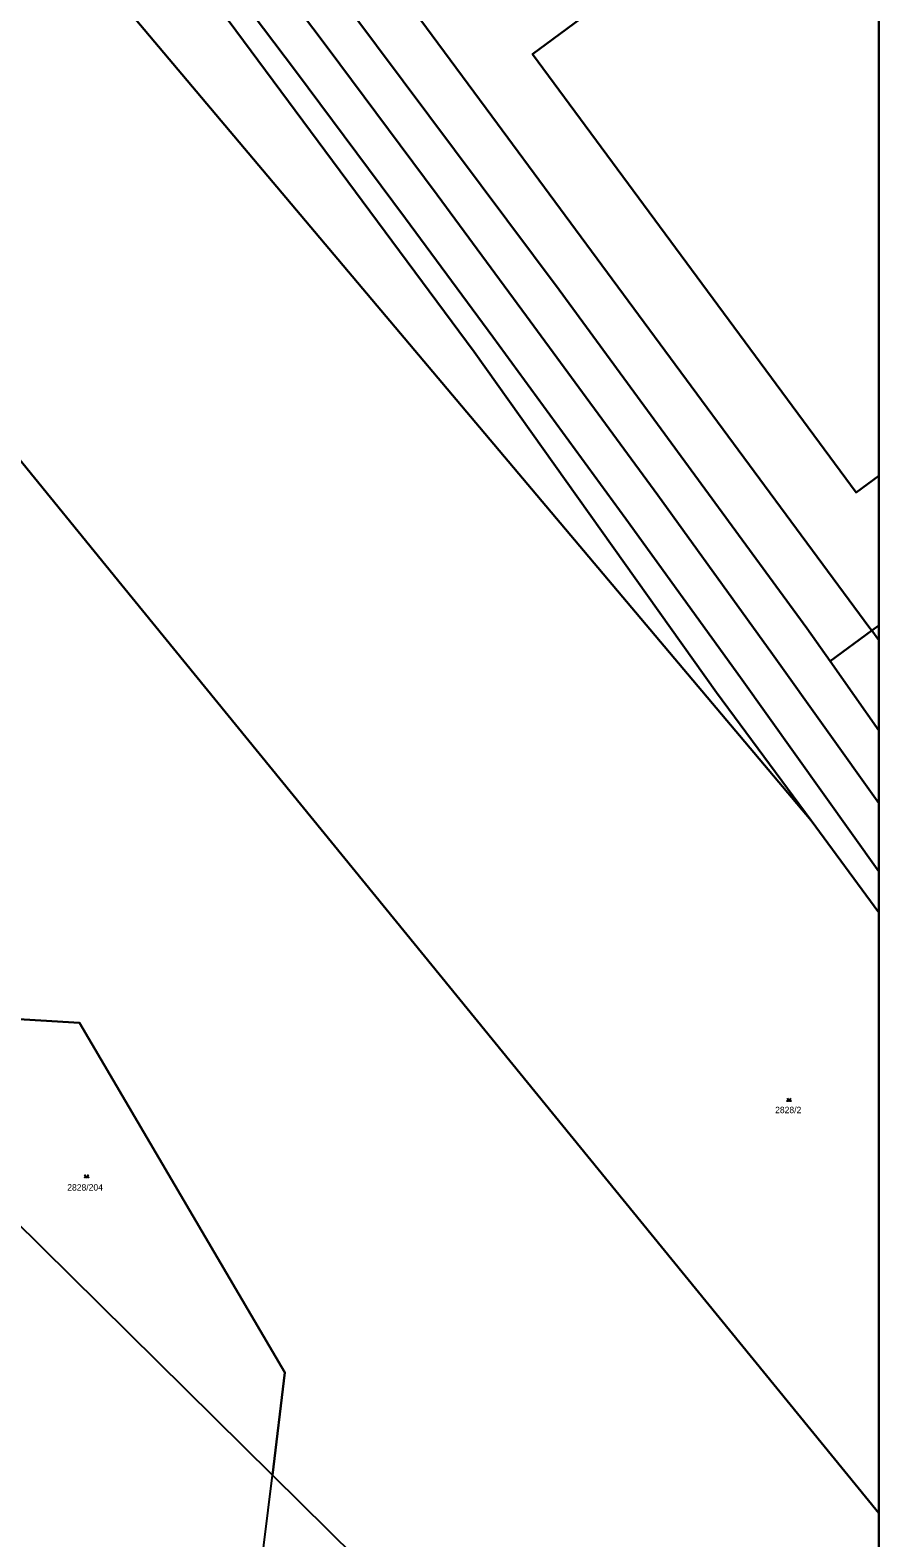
# Model space of a CAD drawing. Extents: x -596024 to -594475, y -1163820 to -1161957.
# Drawn here: x -594701 to -594475.5, y -1163562.3 to -1163161.8 of the extents above; entities that cross this region are included whole.
import ezdxf

# ---------------------------------------------------------------- set-up
doc = ezdxf.new("R2010")
doc.units = 0
for name, color, linetype in [('Level 1', 7, 'Continuous'), ('Level 4', 7, 'Continuous'), ('Level 5', 7, 'Continuous'), ('Level 60', 7, 'Continuous'), ('Vrstva 60', 7, 'Continuous'), ('Vrstva 63', 7, 'Continuous')]:
    doc.layers.add(name, color=color, linetype=linetype)

msp = doc.modelspace()

# ---------------------------------------------------------------- linework, layer by layer
at = {"layer": 'Level 1'}
for p, q in [((-594475.47, -1163319.9), (-594477.35, -1163321.29)), ((-594477.35, -1163321.29), (-594475.47, -1163323.83)), ((-594488.38, -1163329.44), (-594475.47, -1163347.79)), ((-594475.47, -1163396.16), (-594493.49, -1163371.74))]:
    msp.add_line(p, q, dxfattribs=at)
for points in [[(-594911.92, -1162875.41), (-594696.92, -1163130.44), (-594493.49, -1163371.74)], [(-594475.47, -1163367.14), (-594503.72, -1163327.5), (-594534.2, -1163285.34), (-594569.05, -1163237.75), (-594592.79, -1163205.55), (-594622.08, -1163166.28), (-594659.37, -1163116.81), (-594695.79, -1163069.09), (-594743.58, -1163007.45), (-594777.55, -1162964.18), (-594813, -1162919.57), (-594822.85, -1162906.98), (-594831.28, -1162895.79), (-594842.25, -1162879.51)], [(-594493.49, -1163371.74), (-594518.6, -1163337.72), (-594583.03, -1163247.27), (-594671.97, -1163127.18), (-594757.19, -1163016.89), (-594754.76, -1163015.11), (-594823.13, -1162929.61), (-594827.25, -1162921.49), (-594853.89, -1162886.54)], [(-594851.7, -1162885.15), (-594839.81, -1162902.41), (-594830.69, -1162914.32), (-594820.68, -1162926.8), (-594785.89, -1162970.61), (-594751.92, -1163013.83), (-594704.16, -1163075.47), (-594667.76, -1163123.16), (-594630.45, -1163172.62), (-594601.19, -1163211.87), (-594578.06, -1163243.23), (-594542.65, -1163291.6), (-594512.22, -1163333.71), (-594475.47, -1163385.27)], [(-594477.35, -1163321.29), (-594477.83, -1163320.63), (-594578.29, -1163184.64), (-594662.1, -1163071.3), (-594658.25, -1163068.41), (-594661.1, -1163064.47), (-594552.78, -1162984.27), (-594475.47, -1162927.18)], [(-594475.47, -1163555.67), (-594535.93, -1163481.57), (-594603.63, -1163398.6), (-594676.56, -1163309.2), (-594737.79, -1163234.16), (-594811.49, -1163143.83), (-594888.97, -1163048.87)], [(-594488.38, -1163329.44), (-594494.59, -1163320.62), (-594560.41, -1163230.79), (-594650.37, -1163110.35), (-594690.69, -1163058.01)], [(-594553.01, -1163157.5), (-594567.52, -1163168.22), (-594481.49, -1163284.63), (-594475.47, -1163280.18)], [(-594477.35, -1163321.29), (-594488.38, -1163329.44)], [(-594636.61, -1163545.57), (-594633.25, -1163518.34), (-594687.86, -1163425.44), (-594742.22, -1163422.15), (-594795.73, -1163389.03)], [(-594636.61, -1163545.57), (-594736.02, -1163447.41), (-594795.73, -1163389.03)], [(-594498.99, -1163680.49), (-594513.67, -1163715.59), (-594571.07, -1163783.1), (-594661.46, -1163746.33), (-594648.3, -1163639.97), (-594636.61, -1163545.57)], [(-594636.61, -1163545.57), (-594548.15, -1163632.92), (-594498.99, -1163680.49)]]:
    msp.add_lwpolyline(points, dxfattribs=at)
at = {"layer": 'Level 5'}
for points in [[(-594499.87, -1163445.51), (-594499.37, -1163446.26), (-594498.87, -1163445.51)], [(-594686.48, -1163465.77), (-594685.98, -1163466.52), (-594685.48, -1163465.77)]]:
    msp.add_lwpolyline(points, dxfattribs=at)
for centre in [(-594499.82, -1163446.21), (-594498.92, -1163446.21), (-594686.43, -1163466.47), (-594685.53, -1163466.47)]:
    msp.add_circle(centre, 0.05, dxfattribs=at)
at = {"layer": 'Level 60'}
msp.add_lwpolyline([(-594671.97, -1163127.18), (-594583.03, -1163247.27), (-594518.6, -1163337.72), (-594493.49, -1163371.74), (-594696.92, -1163130.44)], dxfattribs=at)
for points in [[(-594633.25, -1163518.34), (-594636.61, -1163545.57), (-594736.02, -1163447.41), (-594795.73, -1163389.03), (-594742.22, -1163422.15), (-594687.86, -1163425.44)], [(-594513.67, -1163715.59), (-594571.07, -1163783.1), (-594661.46, -1163746.33), (-594648.3, -1163639.97), (-594636.61, -1163545.57), (-594548.15, -1163632.92), (-594498.99, -1163680.49)]]:
    msp.add_lwpolyline(points, close=True, dxfattribs=at)
at = {"layer": 'Vrstva 60'}
for points in [[(-594475.47, -1163396.16), (-594493.49, -1163371.74), (-594696.92, -1163130.44), (-594911.92, -1162875.41), (-594891.2, -1162997.68), (-594888.97, -1163048.87), (-594811.49, -1163143.83), (-594737.79, -1163234.16), (-594676.56, -1163309.2), (-594603.63, -1163398.6), (-594535.93, -1163481.57), (-594475.47, -1163555.67)], [(-594475.47, -1163396.16), (-594475.47, -1163385.27), (-594512.22, -1163333.71), (-594542.65, -1163291.6), (-594578.06, -1163243.23), (-594601.19, -1163211.87), (-594630.45, -1163172.62), (-594667.76, -1163123.16), (-594704.16, -1163075.47), (-594751.92, -1163013.83), (-594785.89, -1162970.61), (-594820.68, -1162926.8), (-594830.69, -1162914.32), (-594839.81, -1162902.41), (-594851.7, -1162885.15), (-594853.89, -1162886.54), (-594827.25, -1162921.49), (-594823.13, -1162929.61), (-594754.76, -1163015.11), (-594757.19, -1163016.89), (-594671.97, -1163127.18), (-594583.03, -1163247.27), (-594518.6, -1163337.72), (-594493.49, -1163371.74)], [(-594475.47, -1162927.18), (-594475.47, -1162898.96), (-594557.33, -1162959.45), (-594690.69, -1163058.01), (-594650.37, -1163110.35), (-594560.41, -1163230.79), (-594494.59, -1163320.62), (-594488.38, -1163329.44), (-594477.35, -1163321.29), (-594477.83, -1163320.63), (-594578.29, -1163184.64), (-594662.1, -1163071.3), (-594658.25, -1163068.41), (-594661.1, -1163064.47), (-594552.78, -1162984.27)], [(-594475.47, -1163319.9), (-594475.47, -1163280.18), (-594481.49, -1163284.63), (-594567.52, -1163168.22), (-594553.01, -1163157.5), (-594581.48, -1163118.98), (-594595.99, -1163129.7), (-594639.22, -1163071.2), (-594475.47, -1162950.19), (-594475.47, -1162927.18), (-594552.78, -1162984.27), (-594661.1, -1163064.47), (-594658.25, -1163068.41), (-594662.1, -1163071.3), (-594578.29, -1163184.64), (-594477.83, -1163320.63), (-594477.35, -1163321.29)], [(-594475.47, -1163624.25), (-594475.47, -1163555.67), (-594535.93, -1163481.57), (-594603.63, -1163398.6), (-594676.56, -1163309.2), (-594737.79, -1163234.16), (-594811.49, -1163143.83), (-594888.97, -1163048.87), (-594887.86, -1163075.46), (-594885.09, -1163144.69), (-594884.02, -1163178.01), (-594875.6, -1163310.94), (-594795.73, -1163389.03), (-594742.22, -1163422.15), (-594687.86, -1163425.44), (-594633.25, -1163518.34), (-594636.61, -1163545.57), (-594548.15, -1163632.92), (-594498.99, -1163680.49)], [(-594475.47, -1163280.18), (-594475.47, -1163100.19), (-594547.58, -1163153.48), (-594553.01, -1163157.5), (-594567.52, -1163168.22), (-594481.49, -1163284.63)], [(-594475.47, -1163347.79), (-594475.47, -1163323.83), (-594477.35, -1163321.29), (-594488.38, -1163329.44)], [(-594475.47, -1163323.83), (-594475.47, -1163319.9), (-594477.35, -1163321.29)]]:
    msp.add_lwpolyline(points, close=True, dxfattribs=at)
for points in [[(-594659.37, -1163116.81), (-594622.08, -1163166.28), (-594592.79, -1163205.55), (-594569.05, -1163237.75), (-594534.2, -1163285.34), (-594503.72, -1163327.5), (-594475.47, -1163367.14), (-594475.47, -1163347.79), (-594488.38, -1163329.44), (-594494.59, -1163320.62), (-594560.41, -1163230.79), (-594650.37, -1163110.35)], [(-594667.76, -1163123.16), (-594630.45, -1163172.62), (-594601.19, -1163211.87), (-594578.06, -1163243.23), (-594542.65, -1163291.6), (-594512.22, -1163333.71), (-594475.47, -1163385.27), (-594475.47, -1163367.14), (-594503.72, -1163327.5), (-594534.2, -1163285.34), (-594569.05, -1163237.75), (-594592.79, -1163205.55), (-594622.08, -1163166.28), (-594659.37, -1163116.81)], [(-594881.07, -1163754.37), (-594853.71, -1163759.18), (-594809.52, -1163766.35), (-594779.42, -1163772.07), (-594705.71, -1163784.41), (-594630.48, -1163797), (-594524.52, -1163814.91), (-594475.47, -1163820.23), (-594475.47, -1163703.99), (-594493.09, -1163686.2), (-594498.99, -1163680.49), (-594513.67, -1163715.59), (-594571.07, -1163783.1), (-594661.46, -1163746.33), (-594648.3, -1163639.97), (-594636.61, -1163545.57), (-594736.02, -1163447.41), (-594795.73, -1163389.03), (-594833.98, -1163365.35), (-594876.89, -1163338.79), (-594880.83, -1163384.76)]]:
    msp.add_lwpolyline(points, dxfattribs=at)
at = {"layer": 'Vrstva 63'}
msp.add_lwpolyline([(-594475.47, -1163820.23), (-596024.42, -1163820.23), (-596024.42, -1161956.88), (-594475.47, -1161956.88)], close=True, dxfattribs=at)

# ---------------------------------------------------------------- texts
at = {"layer": 'Level 4'}
for s, p in [('2828/2', (-594503.03, -1163449.46)), ('2828/204', (-594691.1, -1163470.02))]:
    msp.add_text(s, height=1.7, dxfattribs=at).set_placement(p)

doc.saveas('drawing.dxf')
